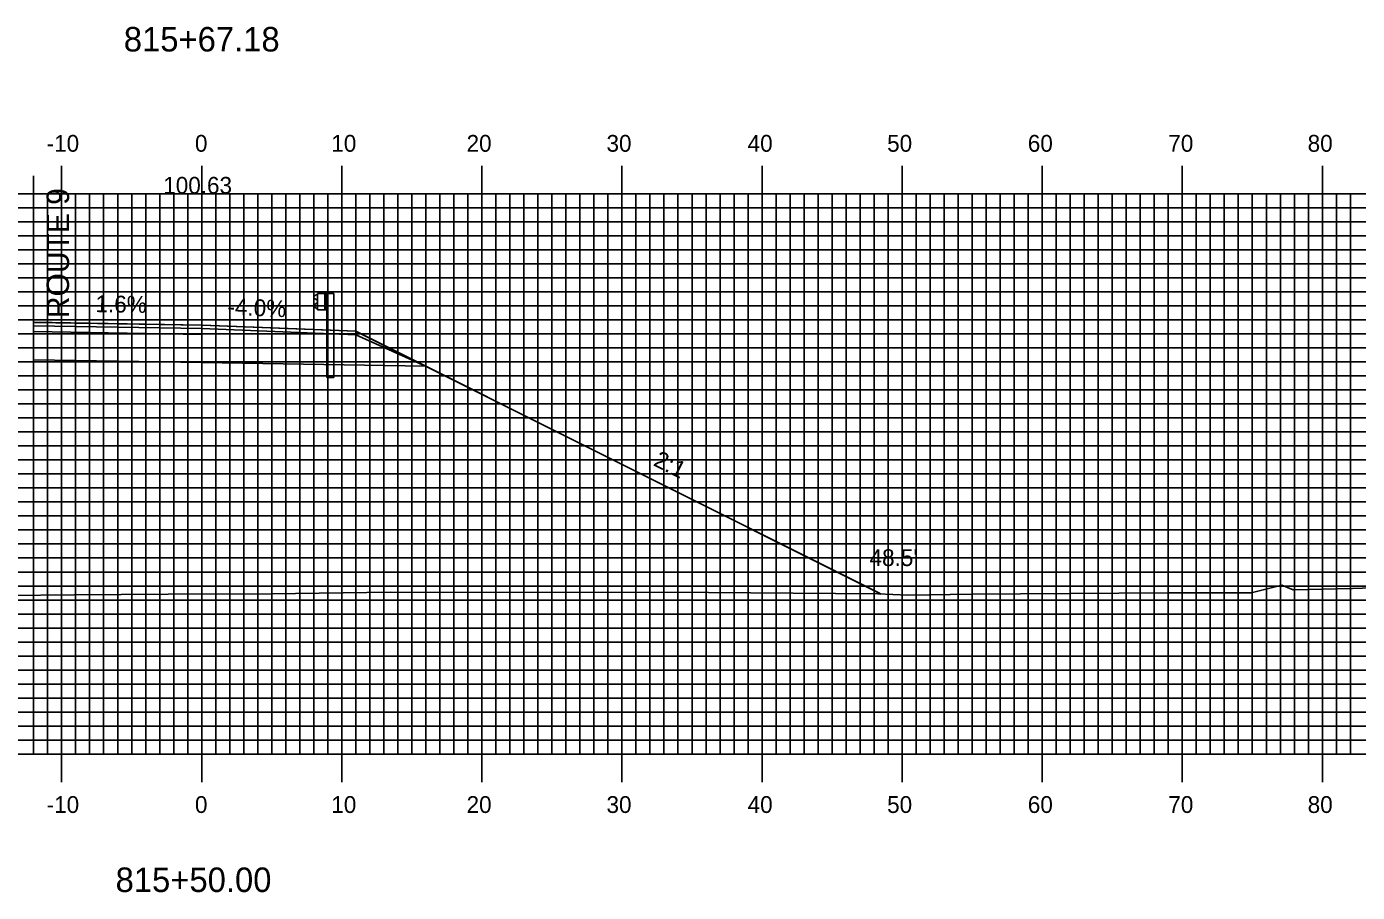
# Model space of a CAD drawing. Extents: x 2846 to 3190, y -1658 to -1438.
# Drawn here: x 2999.7 to 3094.7, y -1589.5 to -1527.7 of the extents above; entities that cross this region are included whole.
import ezdxf

# ---------------------------------------------------------------- set-up
doc = ezdxf.new("R2010")
doc.units = 0
for name, color, linetype in [('ANNOTATION', 7, 'Continuous'), ('D_Guardrail_Beam_Rt', 7, 'Continuous'), ('D_Roadway_Centerline', 7, 'Continuous'), ('D_Roadway_Centerline_Text', 7, 'Continuous'), ('D_Roadway_Edge_Shoulder', 7, 'Continuous'), ('D_Roadway_Edge_TW', 7, 'Continuous'), ('D_Roadway_Pavement', 7, 'Continuous'), ('D_Roadway_SlopeLines', 7, 'Continuous'), ('D_Roadway_SubGrade', 7, 'Continuous'), ('D_Text_Standard', 7, 'Continuous'), ('Default', 7, 'Continuous'), ('H_V ANNOTATION', 7, 'Continuous'), ('MAJOR', 7, 'Continuous'), ('MINOR', 7, 'Continuous'), ('S_Roadway_Centerline', 7, 'Continuous')]:
    doc.layers.add(name, color=color, linetype=linetype)

msp = doc.modelspace()

# ---------------------------------------------------------------- linework, layer by layer
at = {"layer": 'D_Guardrail_Beam_Rt'}
for p, q in [((3020.394, -1546.819), (3020.25, -1546.919)), ((3020.25, -1547.062), (3020.446, -1547.198)), ((3020.446, -1547.397), (3020.25, -1547.533)), ((3020.484, -1546.798), (3020.41, -1546.812)), ((3020.479, -1547.263), (3020.479, -1547.333)), ((3020.484, -1546.714), (3021.171, -1546.714)), ((3020.484, -1547.881), (3020.484, -1546.714)), ((3021.005, -1546.714), (3021.005, -1547.881)), ((3021.109, -1546.714), (3021.109, -1547.881)), ((3021.171, -1546.714), (3021.642, -1546.714)), ((3021.171, -1546.714), (3021.171, -1547.881)), ((3021.642, -1546.714), (3021.642, -1552.714)), ((3020.25, -1547.676), (3020.394, -1547.776)), ((3020.41, -1547.783), (3020.484, -1547.798)), ((3021.171, -1547.881), (3020.484, -1547.881)), ((3021.15, -1552.714), (3021.15, -1547.881)), ((3021.15, -1552.714), (3021.642, -1552.714))]:
    msp.add_line(p, q, dxfattribs=at)
for centre, major_axis, start_param, end_param in [((3020.301, -1546.99), (-0.0877, 0), 5.323254, 7.243116), ((3020.301, -1547.605), (-0.0877, 0), 5.323254, 7.243116), ((3020.418, -1546.853), (-0.0417, 0), 4.907132, 5.323254), ((3020.4, -1547.263), (0.0789, 0), 0, 0.959931), ((3020.4, -1547.333), (0.0789, 0), 5.323254, 6.283185), ((3020.418, -1547.742), (-0.0417, 0), 0.959931, 1.376053)]:
    msp.add_ellipse(centre, major_axis=major_axis, ratio=0.995501, start_param=start_param, end_param=end_param, dxfattribs=at)
at = {"layer": 'D_Roadway_Centerline'}
msp.add_lwpolyline([(3000.213, -1548.78), (3000.213, -1548.78), (3000.302, -1548.782), (3012.213, -1548.978), (3012.272, -1548.98), (3020.213, -1549.298), (3020.235, -1549.299), (3023.213, -1549.418), (3023.25, -1549.436), (3028.179, -1551.901), (3060.493, -1568.058), (3060.727, -1568.175)], dxfattribs=at)
at = {"layer": 'D_Roadway_Edge_Shoulder'}
for points in [[(3012.213, -1548.978), (3023.213, -1549.418), (3023.213, -1549.668), (3012.213, -1549.228)], [(3012.213, -1548.978), (3020.213, -1549.298), (3020.213, -1549.298), (3023.213, -1549.418), (3023.213, -1549.668), (3012.213, -1549.228)], [(3012.213, -1548.978), (3020.213, -1549.298), (3020.213, -1549.298), (3023.213, -1549.418), (3023.213, -1549.668), (3012.213, -1549.228)], [(3012.213, -1548.978), (3023.213, -1549.418), (3023.213, -1549.668), (3012.213, -1549.228)], [(3012.213, -1548.978), (3023.213, -1549.418), (3023.213, -1549.668), (3012.213, -1549.228)]]:
    msp.add_lwpolyline(points, close=True, dxfattribs=at)
at = {"layer": 'D_Roadway_Edge_TW'}
msp.add_lwpolyline([(3000.213, -1548.78), (3012.213, -1548.978), (3012.213, -1549.228), (3000.213, -1549.03)], close=True, dxfattribs=at)
msp.add_lwpolyline([(3000.213, -1548.78), (3012.213, -1548.978), (3012.213, -1549.228), (3000.213, -1549.03)], close=True, dxfattribs=at)
msp.add_lwpolyline([(3000.213, -1548.78), (3012.213, -1548.978), (3012.213, -1549.228), (3000.213, -1549.03)], close=True, dxfattribs=at)
msp.add_lwpolyline([(3000.213, -1548.78), (3012.213, -1548.978), (3012.213, -1549.228), (3000.213, -1549.03)], close=True, dxfattribs=at)
at = {"layer": 'D_Roadway_Pavement'}
msp.add_lwpolyline([(3000.213, -1549.03), (3012.213, -1549.228), (3012.213, -1549.644), (3000.213, -1549.447)], close=True, dxfattribs=at)
msp.add_lwpolyline([(3000.213, -1549.03), (3012.213, -1549.228), (3012.213, -1549.644), (3000.213, -1549.447)], close=True, dxfattribs=at)
msp.add_lwpolyline([(3000.213, -1549.03), (3012.213, -1549.228), (3012.213, -1549.644), (3000.213, -1549.447)], close=True, dxfattribs=at)
msp.add_lwpolyline([(3000.213, -1549.03), (3012.213, -1549.228), (3012.213, -1549.644), (3000.213, -1549.447)], close=True, dxfattribs=at)
msp.add_lwpolyline([(3012.213, -1549.228), (3012.213, -1549.644)], dxfattribs=at)
msp.add_lwpolyline([(3012.213, -1549.228), (3012.213, -1549.644)], dxfattribs=at)
msp.add_lwpolyline([(3012.213, -1549.228), (3012.213, -1549.644)], dxfattribs=at)
msp.add_lwpolyline([(3012.213, -1549.228), (3012.213, -1549.644)], dxfattribs=at)
msp.add_lwpolyline([(3012.213, -1549.228), (3012.213, -1549.644)], dxfattribs=at)
msp.add_lwpolyline([(3012.213, -1549.228), (3012.213, -1549.644)], dxfattribs=at)
msp.add_lwpolyline([(3012.213, -1549.228), (3012.213, -1549.644)], dxfattribs=at)
msp.add_lwpolyline([(3012.213, -1549.228), (3012.213, -1549.644)], dxfattribs=at)
msp.add_lwpolyline([(3012.213, -1549.228), (3012.213, -1549.644)], dxfattribs=at)
msp.add_lwpolyline([(3012.213, -1549.228), (3012.213, -1549.644)], dxfattribs=at)
msp.add_lwpolyline([(3012.213, -1549.228), (3012.213, -1549.644)], dxfattribs=at)
msp.add_lwpolyline([(3012.213, -1549.228), (3012.213, -1549.644)], dxfattribs=at)
msp.add_lwpolyline([(3012.213, -1549.228), (3012.213, -1549.644)], dxfattribs=at)
msp.add_lwpolyline([(3012.213, -1549.228), (3012.213, -1549.644)], dxfattribs=at)
at = {"layer": 'D_Roadway_SlopeLines'}
msp.add_lwpolyline([(3023.213, -1549.418), (3060.727, -1568.175)], dxfattribs=at)
msp.add_lwpolyline([(3023.213, -1549.418), (3060.727, -1568.175)], dxfattribs=at)
msp.add_lwpolyline([(3023.213, -1549.418), (3060.727, -1568.175)], dxfattribs=at)
msp.add_lwpolyline([(3023.213, -1549.418), (3060.727, -1568.175)], dxfattribs=at)
at = {"layer": 'D_Roadway_SubGrade'}
msp.add_line((3000.213, -1538.312), (3000.213, -1551.452), dxfattribs=at)
for points in [[(3000.213, -1549.447), (3012.213, -1549.644), (3012.213, -1551.644), (3000.213, -1551.452)], [(3000.213, -1549.447), (3012.213, -1549.644), (3012.213, -1551.644), (3000.213, -1551.452)], [(3000.213, -1549.447), (3012.213, -1549.644), (3012.213, -1551.644), (3000.213, -1551.452)], [(3000.213, -1549.447), (3012.213, -1549.644), (3012.213, -1551.644), (3000.213, -1551.452)], [(3012.213, -1549.644), (3012.213, -1549.228), (3023.213, -1549.668), (3023.213, -1549.418), (3028.179, -1551.901), (3012.213, -1551.644)], [(3012.213, -1549.644), (3012.213, -1549.228), (3023.213, -1549.668), (3023.213, -1549.418), (3028.179, -1551.901), (3012.213, -1551.644)], [(3012.213, -1549.644), (3012.213, -1549.228), (3023.213, -1549.668), (3023.213, -1549.418), (3028.179, -1551.901), (3012.213, -1551.644)], [(3012.213, -1549.644), (3012.213, -1549.228), (3023.213, -1549.668), (3028.179, -1551.901), (3012.213, -1551.644)], [(3012.213, -1549.644), (3012.213, -1549.228), (3023.213, -1549.668), (3023.213, -1549.418), (3028.179, -1551.901), (3012.213, -1551.644)]]:
    msp.add_lwpolyline(points, close=True, dxfattribs=at)
at = {"layer": 'Default'}
msp.add_line((3000.213, -1551.452), (3000.213, -1547.224), dxfattribs=at)
at = {"layer": 'MAJOR'}
for p, q in [((3002.213, -1537.6), (3002.213, -1539.604)), ((3012.213, -1537.6), (3012.213, -1539.604)), ((3022.213, -1537.6), (3022.213, -1539.604)), ((3032.213, -1537.6), (3032.213, -1539.604)), ((3042.213, -1537.6), (3042.213, -1539.604)), ((3052.213, -1537.6), (3052.213, -1539.604)), ((3062.213, -1537.6), (3062.213, -1539.604)), ((3072.213, -1537.6), (3072.213, -1539.604)), ((3082.213, -1537.6), (3082.213, -1539.604)), ((3092.213, -1537.6), (3092.213, -1539.604)), ((2872.213, -1539.604), (3152.213, -1539.604)), ((2872.213, -1539.604), (3152.213, -1539.604)), ((3002.213, -1579.604), (3002.213, -1539.604)), ((3012.213, -1579.604), (3012.213, -1539.604)), ((3022.213, -1579.604), (3022.213, -1539.604)), ((3032.213, -1579.604), (3032.213, -1539.604)), ((3042.213, -1579.604), (3042.213, -1539.604)), ((3052.213, -1579.604), (3052.213, -1539.604)), ((3062.213, -1579.604), (3062.213, -1539.604)), ((3072.213, -1579.604), (3072.213, -1539.604)), ((3082.213, -1579.604), (3082.213, -1539.604)), ((3092.213, -1579.604), (3092.213, -1539.604)), ((2872.213, -1544.604), (3152.213, -1544.604)), ((2872.213, -1549.604), (3152.213, -1549.604)), ((2872.213, -1554.604), (3152.213, -1554.604)), ((2872.213, -1559.604), (3152.213, -1559.604)), ((2872.213, -1564.604), (3152.213, -1564.604)), ((2872.213, -1569.604), (3152.213, -1569.604)), ((2872.213, -1574.604), (3152.213, -1574.604)), ((2872.213, -1579.604), (3152.213, -1579.604)), ((2872.213, -1579.604), (3152.213, -1579.604)), ((3002.213, -1581.608), (3002.213, -1579.604)), ((3012.213, -1581.608), (3012.213, -1579.604)), ((3022.213, -1581.608), (3022.213, -1579.604)), ((3032.213, -1581.608), (3032.213, -1579.604)), ((3042.213, -1581.608), (3042.213, -1579.604)), ((3052.213, -1581.608), (3052.213, -1579.604)), ((3062.213, -1581.608), (3062.213, -1579.604)), ((3072.213, -1581.608), (3072.213, -1579.604)), ((3082.213, -1581.608), (3082.213, -1579.604)), ((3092.213, -1581.608), (3092.213, -1579.604))]:
    msp.add_line(p, q, dxfattribs=at)
at = {"layer": 'MINOR'}
for p, q in [((3000.213, -1579.604), (3000.213, -1539.604)), ((3001.213, -1579.604), (3001.213, -1539.604)), ((3003.213, -1579.604), (3003.213, -1539.604)), ((3004.213, -1579.604), (3004.213, -1539.604)), ((3005.213, -1579.604), (3005.213, -1539.604)), ((3006.213, -1579.604), (3006.213, -1539.604)), ((3007.213, -1579.604), (3007.213, -1539.604)), ((3008.213, -1579.604), (3008.213, -1539.604)), ((3009.213, -1579.604), (3009.213, -1539.604)), ((3010.213, -1579.604), (3010.213, -1539.604)), ((3011.213, -1579.604), (3011.213, -1539.604)), ((3013.213, -1579.604), (3013.213, -1539.604)), ((3014.213, -1579.604), (3014.213, -1539.604)), ((3015.213, -1579.604), (3015.213, -1539.604)), ((3016.213, -1579.604), (3016.213, -1539.604)), ((3017.213, -1579.604), (3017.213, -1539.604)), ((3018.213, -1579.604), (3018.213, -1539.604)), ((3019.213, -1579.604), (3019.213, -1539.604)), ((3020.213, -1579.604), (3020.213, -1539.604)), ((3021.213, -1579.604), (3021.213, -1539.604)), ((3023.213, -1579.604), (3023.213, -1539.604)), ((3024.213, -1579.604), (3024.213, -1539.604)), ((3025.213, -1579.604), (3025.213, -1539.604)), ((3026.213, -1579.604), (3026.213, -1539.604)), ((3027.213, -1579.604), (3027.213, -1539.604)), ((3028.213, -1579.604), (3028.213, -1539.604)), ((3029.213, -1579.604), (3029.213, -1539.604)), ((3030.213, -1579.604), (3030.213, -1539.604)), ((3031.213, -1579.604), (3031.213, -1539.604)), ((3033.213, -1579.604), (3033.213, -1539.604)), ((3034.213, -1579.604), (3034.213, -1539.604)), ((3035.213, -1579.604), (3035.213, -1539.604)), ((3036.213, -1579.604), (3036.213, -1539.604)), ((3037.213, -1579.604), (3037.213, -1539.604)), ((3038.213, -1579.604), (3038.213, -1539.604)), ((3039.213, -1579.604), (3039.213, -1539.604)), ((3040.213, -1579.604), (3040.213, -1539.604)), ((3041.213, -1579.604), (3041.213, -1539.604)), ((3043.213, -1579.604), (3043.213, -1539.604)), ((3044.213, -1579.604), (3044.213, -1539.604)), ((3045.213, -1579.604), (3045.213, -1539.604)), ((3046.213, -1579.604), (3046.213, -1539.604)), ((3047.213, -1579.604), (3047.213, -1539.604)), ((3048.213, -1579.604), (3048.213, -1539.604)), ((3049.213, -1579.604), (3049.213, -1539.604)), ((3050.213, -1579.604), (3050.213, -1539.604)), ((3051.213, -1579.604), (3051.213, -1539.604)), ((3053.213, -1579.604), (3053.213, -1539.604)), ((3054.213, -1579.604), (3054.213, -1539.604)), ((3055.213, -1579.604), (3055.213, -1539.604)), ((3056.213, -1579.604), (3056.213, -1539.604)), ((3057.213, -1579.604), (3057.213, -1539.604)), ((3058.213, -1579.604), (3058.213, -1539.604)), ((3059.213, -1579.604), (3059.213, -1539.604)), ((3060.213, -1579.604), (3060.213, -1539.604)), ((3061.213, -1579.604), (3061.213, -1539.604)), ((3063.213, -1579.604), (3063.213, -1539.604)), ((3064.213, -1579.604), (3064.213, -1539.604)), ((3065.213, -1579.604), (3065.213, -1539.604)), ((3066.213, -1579.604), (3066.213, -1539.604)), ((3067.213, -1579.604), (3067.213, -1539.604)), ((3068.213, -1579.604), (3068.213, -1539.604)), ((3069.213, -1579.604), (3069.213, -1539.604)), ((3070.213, -1579.604), (3070.213, -1539.604)), ((3071.213, -1579.604), (3071.213, -1539.604)), ((3073.213, -1579.604), (3073.213, -1539.604)), ((3074.213, -1579.604), (3074.213, -1539.604)), ((3075.213, -1579.604), (3075.213, -1539.604)), ((3076.213, -1579.604), (3076.213, -1539.604)), ((3077.213, -1579.604), (3077.213, -1539.604)), ((3078.213, -1579.604), (3078.213, -1539.604)), ((3079.213, -1579.604), (3079.213, -1539.604)), ((3080.213, -1579.604), (3080.213, -1539.604)), ((3081.213, -1579.604), (3081.213, -1539.604)), ((3083.213, -1579.604), (3083.213, -1539.604)), ((3084.213, -1579.604), (3084.213, -1539.604)), ((3085.213, -1579.604), (3085.213, -1539.604)), ((3086.213, -1579.604), (3086.213, -1539.604)), ((3087.213, -1579.604), (3087.213, -1539.604)), ((3088.213, -1579.604), (3088.213, -1539.604)), ((3089.213, -1579.604), (3089.213, -1539.604)), ((3090.213, -1579.604), (3090.213, -1539.604)), ((3091.213, -1579.604), (3091.213, -1539.604)), ((3093.213, -1579.604), (3093.213, -1539.604)), ((3094.213, -1579.604), (3094.213, -1539.604)), ((2872.213, -1540.604), (3152.213, -1540.604)), ((2872.213, -1541.604), (3152.213, -1541.604)), ((2872.213, -1542.604), (3152.213, -1542.604)), ((2872.213, -1543.604), (3152.213, -1543.604)), ((2872.213, -1545.604), (3152.213, -1545.604)), ((2872.213, -1546.604), (3152.213, -1546.604)), ((2872.213, -1547.604), (3152.213, -1547.604)), ((2872.213, -1548.604), (3152.213, -1548.604)), ((2872.213, -1550.604), (3152.213, -1550.604)), ((2872.213, -1551.604), (3152.213, -1551.604)), ((2872.213, -1552.604), (3152.213, -1552.604)), ((2872.213, -1553.604), (3152.213, -1553.604)), ((2872.213, -1555.604), (3152.213, -1555.604)), ((2872.213, -1556.604), (3152.213, -1556.604)), ((2872.213, -1557.604), (3152.213, -1557.604)), ((2872.213, -1558.604), (3152.213, -1558.604)), ((2872.213, -1560.604), (3152.213, -1560.604)), ((2872.213, -1561.604), (3152.213, -1561.604)), ((2872.213, -1562.604), (3152.213, -1562.604)), ((2872.213, -1563.604), (3152.213, -1563.604)), ((2872.213, -1565.604), (3152.213, -1565.604)), ((2872.213, -1566.604), (3152.213, -1566.604)), ((2872.213, -1567.604), (3152.213, -1567.604)), ((2872.213, -1568.604), (3152.213, -1568.604)), ((2872.213, -1570.604), (3152.213, -1570.604)), ((2872.213, -1571.604), (3152.213, -1571.604)), ((2872.213, -1572.604), (3152.213, -1572.604)), ((2872.213, -1573.604), (3152.213, -1573.604)), ((2872.213, -1575.604), (3152.213, -1575.604)), ((2872.213, -1576.604), (3152.213, -1576.604)), ((2872.213, -1577.604), (3152.213, -1577.604)), ((2872.213, -1578.604), (3152.213, -1578.604))]:
    msp.add_line(p, q, dxfattribs=at)
at = {"layer": 'S_Roadway_Centerline'}
msp.add_lwpolyline([(2998.335, -1568.275), (3003.101, -1568.245), (3009.817, -1568.191), (3017.199, -1568.151), (3025.708, -1568.035), (3048.394, -1568.057), (3060.49, -1568.165), (3062.612, -1568.257), (3067.173, -1568.175), (3081.193, -1568.079), (3087.12, -1568.079), (3089.326, -1567.555), (3090.14, -1567.875), (3094.36, -1567.773), (3095.783, -1567.742)], dxfattribs=at)

# ---------------------------------------------------------------- texts
at = {"layer": 'ANNOTATION'}
for s, height, rotation, p in [('ROUTE 9', 1.6, 90, (3002.744, -1548.479)), ('1.6%', 1.2, 359.0575, (3004.621, -1548.052)), ('-4.0%', 1.2, 357.70939, (3014.034, -1548.249)), ('2:1', 1.2, 333.43495, (3044.387, -1558.969))]:
    msp.add_text(s, height=height, rotation=rotation, dxfattribs=at).set_placement(p)
at = {"layer": 'D_Roadway_Centerline_Text'}
msp.add_text('100.63', height=1.2, dxfattribs=at).set_placement((3009.468, -1539.601))
at = {"layer": 'D_Text_Standard'}
msp.add_text("48.5'", height=1.2, dxfattribs=at).set_placement((3059.891, -1566.18))
at = {"layer": 'H_V ANNOTATION'}
for s, height, p in [('815+67.18', 1.75, (3006.65, -1529.448)), ('-10', 1.2, (3001.143, -1536.604)), ('0', 1.2, (3011.731, -1536.604)), ('10', 1.2, (3021.464, -1536.604)), ('20', 1.2, (3031.121, -1536.604)), ('30', 1.2, (3041.11, -1536.604)), ('40', 1.2, (3051.185, -1536.604)), ('50', 1.2, (3061.142, -1536.604)), ('60', 1.2, (3071.185, -1536.604)), ('70', 1.2, (3081.217, -1536.604)), ('80', 1.2, (3091.164, -1536.604)), ('-10', 1.2, (3001.143, -1583.804)), ('0', 1.2, (3011.731, -1583.804)), ('10', 1.2, (3021.464, -1583.804)), ('20', 1.2, (3031.121, -1583.804)), ('30', 1.2, (3041.11, -1583.804)), ('40', 1.2, (3051.185, -1583.804)), ('50', 1.2, (3061.142, -1583.804)), ('60', 1.2, (3071.185, -1583.804)), ('70', 1.2, (3081.217, -1583.804)), ('80', 1.2, (3091.164, -1583.804)), ('815+50.00', 1.75, (3006.064, -1589.448))]:
    msp.add_text(s, height=height, dxfattribs=at).set_placement(p)

doc.saveas('drawing.dxf')
